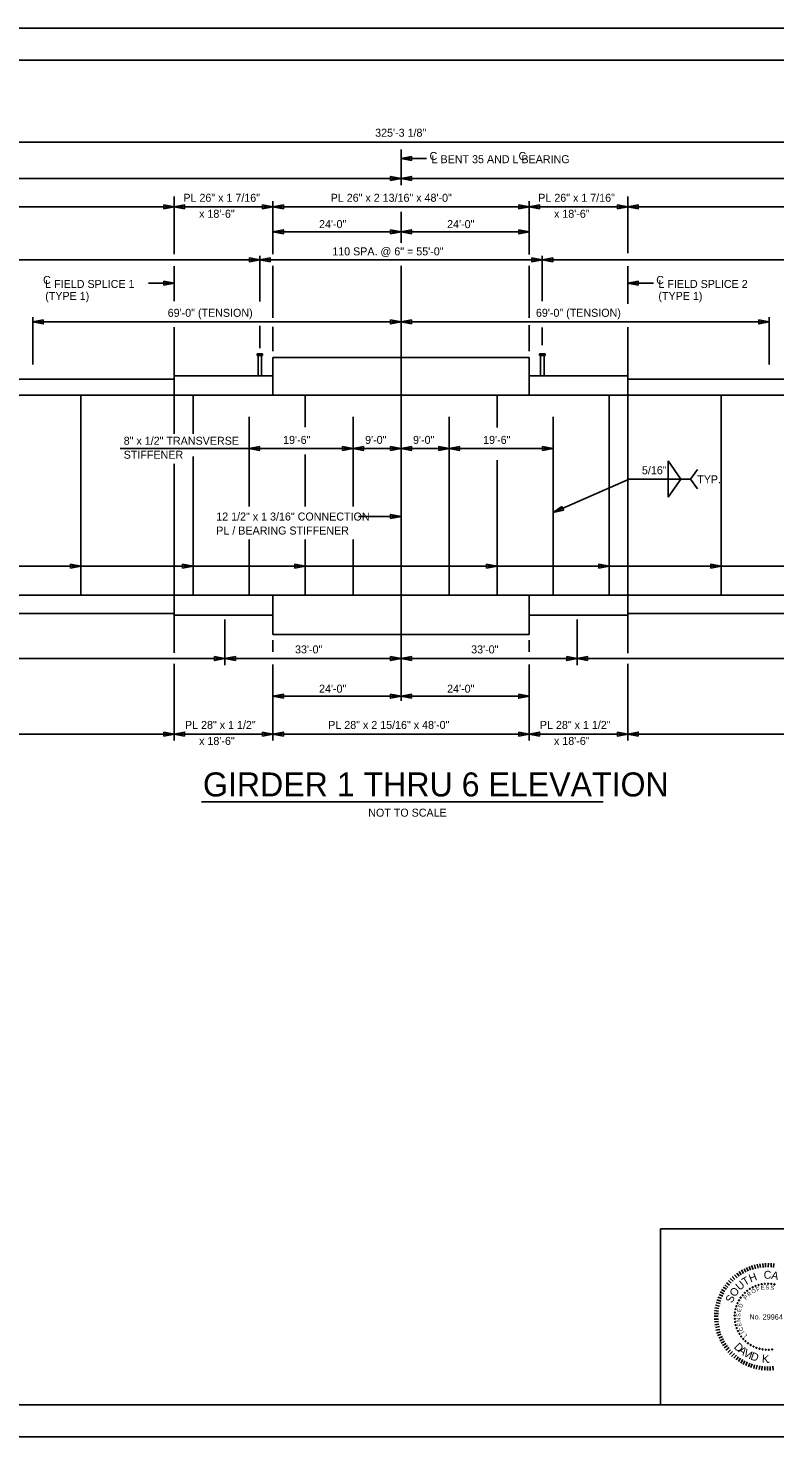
# Model space of a CAD drawing. Extents: x -305 to -161, y -187 to -99.
# Drawn here: x -254.1 to -207.5, y -187.5 to -99.5 of the extents above; entities that cross this region are included whole.
import ezdxf

# ---------------------------------------------------------------- set-up
doc = ezdxf.new("R2010")
doc.units = 0
for name, color, linetype in [('BR_AUTO DIMENSION', 7, 'Continuous'), ('BR_BORDER LINES', 7, 'Continuous'), ('BR_CENTER LINES', 7, 'Continuous'), ('BR_STRUCTURAL STEEL', 7, 'Continuous'), ('BR_TEXT', 7, 'Continuous'), ('Default', 7, 'Continuous'), ('Level 31', 7, 'Continuous')]:
    doc.layers.add(name, color=color, linetype=linetype)

msp = doc.modelspace()

# ---------------------------------------------------------------- linework, layer by layer
at = {"layer": 'BR_AUTO DIMENSION'}
for p, q in [((-285.058, -106.618), (-176.638, -106.618)), ((-230.848, -107.634), (-229.249, -107.634)), ((-285.058, -108.876), (-230.848, -108.876)), ((-230.848, -108.876), (-176.638, -108.876)), ((-245.014, -110.653), (-285.055, -110.653)), ((-238.848, -110.653), (-245.014, -110.653)), ((-238.848, -110.296), (-238.848, -113.612)), ((-238.848, -110.653), (-222.848, -110.653)), ((-222.848, -110.296), (-222.848, -113.63)), ((-222.848, -110.653), (-216.681, -110.653)), ((-176.638, -110.653), (-216.681, -110.653)), ((-230.848, -112.204), (-238.848, -112.204)), ((-222.848, -112.204), (-230.848, -112.204)), ((-178.638, -113.971), (-279.742, -113.971)), ((-239.668, -116.573), (-239.668, -113.71)), ((-238.848, -114.345), (-238.848, -117.575)), ((-222.848, -114.345), (-222.848, -117.575)), ((-222.028, -116.545), (-222.028, -113.71)), ((-245.014, -115.428), (-246.613, -115.428)), ((-216.681, -115.428), (-215.082, -115.428)), ((-253.848, -117.55), (-253.848, -120.501)), ((-253.848, -117.84), (-230.848, -117.84)), ((-207.848, -117.84), (-230.848, -117.84)), ((-207.848, -117.55), (-207.848, -120.501)), ((-239.668, -119.487), (-239.668, -118.076)), ((-238.848, -118.143), (-238.848, -119.661)), ((-222.848, -118.051), (-222.848, -119.661)), ((-222.028, -119.285), (-222.028, -118.194)), ((-248.394, -125.748), (-233.848, -125.748)), ((-233.848, -125.748), (-230.848, -125.748)), ((-230.848, -125.748), (-227.848, -125.748)), ((-227.848, -125.748), (-221.354, -125.748)), ((-214.174, -126.524), (-214.174, -128.791)), ((-214.174, -126.524), (-213.369, -127.657)), ((-212.766, -127.657), (-212.333, -127.05)), ((-216.59, -127.657), (-221.354, -129.746)), ((-216.59, -127.657), (-212.766, -127.657)), ((-214.174, -128.791), (-213.369, -127.657)), ((-212.766, -127.657), (-212.333, -128.265)), ((-230.848, -129.991), (-233.496, -129.991)), ((-182.854, -133.101), (-289.275, -133.101)), ((-241.848, -136.437), (-241.848, -139.273)), ((-219.848, -136.437), (-219.848, -139.273)), ((-238.848, -137.729), (-238.848, -138.442)), ((-222.848, -137.729), (-222.848, -138.442)), ((-241.848, -138.867), (-285.058, -138.867)), ((-230.848, -138.867), (-241.848, -138.867)), ((-219.848, -138.867), (-230.848, -138.867)), ((-176.638, -138.867), (-219.848, -138.867)), ((-238.848, -139.243), (-238.848, -143.986)), ((-222.848, -139.243), (-222.848, -143.986)), ((-230.848, -141.226), (-238.848, -141.226)), ((-222.848, -141.226), (-230.848, -141.226)), ((-285.055, -143.585), (-245.014, -143.585)), ((-245.014, -143.585), (-238.848, -143.585)), ((-238.848, -143.585), (-222.848, -143.585)), ((-222.848, -143.585), (-216.681, -143.585)), ((-216.681, -143.585), (-176.638, -143.585))]:
    msp.add_line(p, q, dxfattribs=at)
for points in [[(-230.198, -107.759), (-230.848, -107.634), (-230.198, -107.509)], [(-231.498, -109.001), (-230.848, -108.876), (-231.498, -108.751)], [(-230.198, -109.001), (-230.848, -108.876), (-230.198, -108.751)], [(-245.664, -110.778), (-245.014, -110.653), (-245.664, -110.528)], [(-244.364, -110.778), (-245.014, -110.653), (-244.364, -110.528)], [(-239.498, -110.778), (-238.848, -110.653), (-239.498, -110.528)], [(-238.198, -110.778), (-238.848, -110.653), (-238.198, -110.528)], [(-223.498, -110.778), (-222.848, -110.653), (-223.498, -110.528)], [(-222.198, -110.778), (-222.848, -110.653), (-222.198, -110.528)], [(-217.331, -110.778), (-216.681, -110.653), (-217.331, -110.528)], [(-216.031, -110.778), (-216.681, -110.653), (-216.031, -110.528)], [(-238.198, -112.329), (-238.848, -112.204), (-238.198, -112.079)], [(-231.498, -112.079), (-230.848, -112.204), (-231.498, -112.329)], [(-230.198, -112.329), (-230.848, -112.204), (-230.198, -112.079)], [(-223.498, -112.079), (-222.848, -112.204), (-223.498, -112.329)], [(-240.318, -114.096), (-239.668, -113.971), (-240.318, -113.846)], [(-239.018, -114.096), (-239.668, -113.971), (-239.018, -113.846)], [(-222.678, -114.096), (-222.028, -113.971), (-222.678, -113.846)], [(-221.378, -114.096), (-222.028, -113.971), (-221.378, -113.846)], [(-245.664, -115.553), (-245.014, -115.428), (-245.664, -115.303)], [(-216.031, -115.553), (-216.681, -115.428), (-216.031, -115.303)], [(-253.198, -117.715), (-253.848, -117.84), (-253.198, -117.965)], [(-231.498, -117.715), (-230.848, -117.84), (-231.498, -117.965)], [(-230.198, -117.965), (-230.848, -117.84), (-230.198, -117.715)], [(-208.498, -117.715), (-207.848, -117.84), (-208.498, -117.965)], [(-239.69, -125.623), (-240.34, -125.748), (-239.69, -125.873)], [(-234.498, -125.873), (-233.848, -125.748), (-234.498, -125.623)], [(-233.198, -125.623), (-233.848, -125.748), (-233.198, -125.873)], [(-231.498, -125.873), (-230.848, -125.748), (-231.498, -125.623)], [(-230.198, -125.623), (-230.848, -125.748), (-230.198, -125.873)], [(-228.498, -125.873), (-227.848, -125.748), (-228.498, -125.623)], [(-227.198, -125.623), (-227.848, -125.748), (-227.198, -125.873)], [(-222.004, -125.873), (-221.354, -125.748), (-222.004, -125.623)], [(-231.498, -130.116), (-230.848, -129.991), (-231.498, -129.866)], [(-220.809, -129.371), (-221.354, -129.746), (-220.708, -129.6)], [(-251.49, -133.226), (-250.84, -133.101), (-251.49, -132.976)], [(-244.49, -133.226), (-243.84, -133.101), (-244.49, -132.976)], [(-237.49, -133.226), (-236.84, -133.101), (-237.49, -132.976)], [(-225.504, -133.226), (-224.854, -133.101), (-225.504, -132.976)], [(-218.504, -133.226), (-217.854, -133.101), (-218.504, -132.976)], [(-211.504, -133.226), (-210.854, -133.101), (-211.504, -132.976)], [(-242.498, -138.742), (-241.848, -138.867), (-242.498, -138.992)], [(-241.198, -138.992), (-241.848, -138.867), (-241.198, -138.742)], [(-231.498, -138.742), (-230.848, -138.867), (-231.498, -138.992)], [(-230.198, -138.992), (-230.848, -138.867), (-230.198, -138.742)], [(-220.498, -138.742), (-219.848, -138.867), (-220.498, -138.992)], [(-219.198, -138.992), (-219.848, -138.867), (-219.198, -138.742)], [(-238.198, -141.351), (-238.848, -141.226), (-238.198, -141.101)], [(-231.498, -141.101), (-230.848, -141.226), (-231.498, -141.351)], [(-230.198, -141.351), (-230.848, -141.226), (-230.198, -141.101)], [(-223.498, -141.101), (-222.848, -141.226), (-223.498, -141.351)], [(-245.664, -143.46), (-245.014, -143.585), (-245.664, -143.71)], [(-244.364, -143.71), (-245.014, -143.585), (-244.364, -143.46)], [(-239.498, -143.46), (-238.848, -143.585), (-239.498, -143.71)], [(-238.198, -143.71), (-238.848, -143.585), (-238.198, -143.46)], [(-223.498, -143.46), (-222.848, -143.585), (-223.498, -143.71)], [(-222.198, -143.71), (-222.848, -143.585), (-222.198, -143.46)], [(-217.331, -143.46), (-216.681, -143.585), (-217.331, -143.71)], [(-216.031, -143.71), (-216.681, -143.585), (-216.031, -143.46)]]:
    msp.add_lwpolyline(points, close=True, dxfattribs=at)
at = {"layer": 'BR_BORDER LINES'}
for p, q in [((-163.178, -101.489), (-297.843, -101.489)), ((-214.64, -174.489), (-193.18, -174.489)), ((-214.64, -185.489), (-214.64, -174.489)), ((-297.843, -185.489), (-163.178, -185.489))]:
    msp.add_line(p, q, dxfattribs=at)
at = {"layer": 'BR_CENTER LINES'}
for p, q in [((-230.848, -107.059), (-230.848, -109.303)), ((-245.014, -109.997), (-245.014, -113.616)), ((-216.681, -109.997), (-216.681, -113.552)), ((-230.848, -110.967), (-230.848, -112.902)), ((-245.014, -114.353), (-245.014, -116.546)), ((-230.848, -114.337), (-230.848, -122.412)), ((-216.681, -114.353), (-216.681, -116.705)), ((-245.014, -118.172), (-245.014, -124.828)), ((-216.681, -118.172), (-216.681, -138.538)), ((-245.014, -126.695), (-245.014, -138.52)), ((-230.848, -134.912), (-230.848, -141.514)), ((-245.014, -139.198), (-245.014, -143.986)), ((-216.681, -139.198), (-216.681, -143.986))]:
    msp.add_line(p, q, dxfattribs=at)
at = {"layer": 'BR_STRUCTURAL STEEL'}
for p, q in [((-238.848, -120.069), (-222.848, -120.069)), ((-238.848, -122.412), (-238.848, -120.069)), ((-222.848, -122.412), (-222.848, -120.069)), ((-285.058, -121.423), (-245.014, -121.423)), ((-245.014, -121.215), (-245.014, -122.412)), ((-245.014, -121.215), (-238.848, -121.215)), ((-222.848, -121.215), (-216.681, -121.215)), ((-216.681, -121.215), (-216.681, -122.412)), ((-216.681, -121.423), (-176.638, -121.423)), ((-285.058, -122.412), (-176.638, -122.412)), ((-250.84, -122.412), (-250.84, -134.912)), ((-243.84, -122.412), (-243.84, -124.828)), ((-236.84, -122.412), (-236.84, -124.407)), ((-230.848, -122.412), (-230.848, -134.912)), ((-224.854, -122.412), (-224.854, -124.436)), ((-217.854, -122.412), (-217.854, -134.912)), ((-210.854, -122.412), (-210.854, -134.912)), ((-240.34, -123.779), (-240.34, -129.362)), ((-233.848, -123.779), (-233.848, -129.362)), ((-227.848, -123.779), (-227.848, -134.912)), ((-221.354, -123.779), (-221.354, -134.912)), ((-243.84, -126.24), (-243.84, -134.912)), ((-236.84, -126.13), (-236.84, -129.362)), ((-224.854, -126.467), (-224.854, -134.912)), ((-240.34, -131.431), (-240.34, -134.912)), ((-236.84, -131.431), (-236.84, -134.912)), ((-233.848, -131.431), (-233.848, -134.912)), ((-285.058, -134.912), (-176.638, -134.912)), ((-245.014, -134.912), (-245.014, -136.162)), ((-238.848, -137.36), (-238.848, -134.912)), ((-222.848, -137.36), (-222.848, -134.912)), ((-216.681, -136.162), (-216.681, -134.912)), ((-285.058, -136.058), (-245.014, -136.058)), ((-245.014, -136.162), (-238.848, -136.162)), ((-222.848, -136.162), (-216.681, -136.162)), ((-216.681, -136.058), (-176.638, -136.058)), ((-238.848, -137.36), (-222.848, -137.36))]:
    msp.add_line(p, q, dxfattribs=at)
at = {"layer": 'BR_TEXT'}
for p, q in [((-243.307, -147.82), (-218.234, -147.82)), ((-209.02, -177.076), (-209.103, -176.842)), ((-208.861, -177.026), (-208.949, -176.795)), ((-208.717, -176.986), (-208.77, -176.742)), ((-208.552, -176.946), (-208.608, -176.709)), ((-208.394, -176.917), (-208.429, -176.673)), ((-208.236, -176.901), (-208.251, -176.657)), ((-208.077, -176.892), (-208.075, -176.634)), ((-207.909, -176.883), (-207.907, -176.636)), ((-207.741, -176.895), (-207.732, -176.637)), ((-207.58, -176.906), (-207.561, -176.663)), ((-210.228, -177.894), (-210.402, -177.724)), ((-210.11, -177.771), (-210.287, -177.594)), ((-209.993, -177.662), (-210.159, -177.482)), ((-209.861, -177.564), (-210.021, -177.363)), ((-209.726, -177.462), (-209.883, -177.258)), ((-209.602, -177.377), (-209.724, -177.16)), ((-209.461, -177.282), (-209.582, -177.065)), ((-209.323, -177.211), (-209.427, -176.987)), ((-209.175, -177.144), (-209.269, -176.92)), ((-210.756, -178.699), (-210.985, -178.598)), ((-210.686, -178.552), (-210.912, -178.441)), ((-210.617, -178.416), (-210.832, -178.287)), ((-210.519, -178.269), (-210.734, -178.137)), ((-210.432, -178.153), (-210.63, -177.993)), ((-210.328, -178.02), (-210.526, -177.864)), ((-210.996, -179.47), (-211.24, -179.437)), ((-210.954, -179.326), (-211.204, -179.262)), ((-210.925, -179.158), (-211.168, -179.098)), ((-210.876, -179.014), (-211.122, -178.923)), ((-210.826, -178.853), (-211.059, -178.766)), ((-211.029, -180.129), (-211.286, -180.133)), ((-211.034, -179.957), (-211.285, -179.955)), ((-211.026, -179.792), (-211.284, -179.79)), ((-211.02, -180.283), (-211.267, -180.312)), ((-211.015, -179.634), (-211.261, -179.605)), ((-211.004, -180.448), (-211.248, -180.484)), ((-210.964, -180.606), (-211.215, -180.659)), ((-210.938, -180.775), (-211.182, -180.831)), ((-210.891, -180.923), (-211.139, -181.006)), ((-210.845, -181.077), (-211.079, -181.161)), ((-210.777, -181.226), (-211.008, -181.334)), ((-210.71, -181.37), (-210.937, -181.489)), ((-210.642, -181.519), (-210.859, -181.644)), ((-210.547, -181.667), (-210.765, -181.792)), ((-210.462, -181.784), (-210.663, -181.93)), ((-210.361, -181.919), (-210.561, -182.075)), ((-210.262, -182.054), (-210.439, -182.217)), ((-210.146, -182.158), (-210.326, -182.338)), ((-210.031, -182.279), (-210.2, -182.463)), ((-209.901, -182.383), (-210.064, -182.57)), ((-209.768, -182.487), (-209.927, -182.678)), ((-209.645, -182.574), (-209.77, -182.782)), ((-209.505, -182.664), (-209.63, -182.879)), ((-209.368, -182.744), (-209.477, -182.967)), ((-209.221, -182.814), (-209.319, -183.037)), ((-209.068, -182.884), (-209.155, -183.11)), ((-208.91, -182.933), (-209.001, -183.166)), ((-208.766, -182.983), (-208.823, -183.219)), ((-208.602, -183.011), (-208.662, -183.258)), ((-208.444, -183.058), (-208.484, -183.29)), ((-208.287, -183.076), (-208.306, -183.323)), ((-208.129, -183.087), (-208.131, -183.335)), ((-207.961, -183.099), (-207.963, -183.343)), ((-207.792, -183.09), (-207.787, -183.338)), ((-207.631, -183.081), (-207.616, -183.329))]:
    msp.add_line(p, q, dxfattribs=at)
for centre, start, end in [((-209.51, -178.639), 49.37299, 229.37299), ((-209.51, -178.639), 229.37299, 49.37299), ((-209.373, -178.495), 43.83453, 223.83453), ((-209.373, -178.495), 223.83453, 43.83453), ((-209.223, -178.364), 38.29606, 218.29606), ((-209.223, -178.364), 218.29606, 38.29606), ((-209.06, -178.248), 32.7576, 212.7576), ((-209.06, -178.248), 212.7576, 32.7576), ((-208.887, -178.149), 27.21914, 207.21914), ((-208.887, -178.149), 207.21914, 27.21914), ((-208.706, -178.067), 21.68068, 201.68068), ((-208.706, -178.067), 201.68068, 21.68068), ((-208.517, -178.003), 16.14222, 196.14222), ((-208.517, -178.003), 196.14222, 16.14222), ((-208.323, -177.957), 10.60376, 190.60376), ((-208.323, -177.957), 190.60376, 10.60376), ((-208.126, -177.93), 5.06529, 185.06529), ((-208.126, -177.93), 185.06529, 5.06529), ((-207.926, -177.923), 359.52683, 179.52683), ((-207.926, -177.923), 179.52683, 359.52683), ((-207.727, -177.934), 353.98837, 173.98837), ((-207.727, -177.934), 173.98837, 353.98837), ((-207.531, -177.965), 168.44991, 348.44991), ((-207.531, -177.965), 348.44991, 168.44991), ((-209.957, -179.52), 77.06529, 257.06529), ((-209.957, -179.52), 257.06529, 77.06529), ((-209.903, -179.328), 71.52683, 251.52683), ((-209.903, -179.328), 251.52683, 71.52683), ((-209.83, -179.142), 65.98837, 245.98837), ((-209.83, -179.142), 245.98837, 65.98837), ((-209.74, -178.964), 60.44991, 240.44991), ((-209.74, -178.964), 240.44991, 60.44991), ((-209.633, -178.796), 54.91145, 234.91145), ((-209.633, -178.796), 234.91145, 54.91145), ((-210.009, -179.914), 88.14222, 268.14222), ((-210.006, -180.114), 93.68068, 273.68068), ((-209.993, -179.716), 82.60376, 262.60376), ((-209.984, -180.312), 99.21914, 279.21914), ((-210.009, -179.914), 268.14222, 88.14222), ((-210.006, -180.114), 273.68068, 93.68068), ((-209.993, -179.716), 262.60376, 82.60376), ((-209.984, -180.312), 279.21914, 99.21914), ((-209.943, -180.507), 104.7576, 284.7576), ((-209.943, -180.507), 284.7576, 104.7576), ((-209.884, -180.697), 110.29606, 290.29606), ((-209.884, -180.697), 290.29606, 110.29606), ((-209.806, -180.881), 115.83453, 295.83453), ((-209.806, -180.881), 295.83453, 115.83453), ((-209.711, -181.056), 121.37299, 301.37299), ((-209.711, -181.056), 301.37299, 121.37299), ((-209.599, -181.221), 126.91145, 306.91145), ((-209.599, -181.221), 306.91145, 126.91145), ((-209.472, -181.375), 132.44991, 312.44991), ((-209.472, -181.375), 312.44991, 132.44991), ((-209.331, -181.515), 137.98837, 317.98837), ((-209.331, -181.515), 317.98837, 137.98837), ((-209.177, -181.642), 143.52683, 323.52683), ((-209.177, -181.642), 323.52683, 143.52683), ((-209.011, -181.753), 149.06529, 329.06529), ((-209.011, -181.753), 329.06529, 149.06529), ((-208.836, -181.847), 154.60376, 334.60376), ((-208.836, -181.847), 334.60376, 154.60376), ((-208.652, -181.924), 160.14222, 340.14222), ((-208.652, -181.924), 340.14222, 160.14222), ((-208.462, -181.983), 165.68068, 345.68068), ((-208.462, -181.983), 345.68068, 165.68068), ((-208.267, -182.023), 171.21914, 351.21914), ((-208.267, -182.023), 351.21914, 171.21914), ((-208.068, -182.045), 356.7576, 176.7576), ((-208.068, -182.045), 176.7576, 356.7576), ((-207.869, -182.047), 2.29606, 182.29606), ((-207.869, -182.047), 182.29606, 2.29606), ((-207.67, -182.029), 7.83453, 187.83453), ((-207.67, -182.029), 187.83453, 7.83453)]:
    msp.add_arc(centre, 0.028, start, end, dxfattribs=at)
at = {"layer": 'Default'}
for p, q in [((-239.839, -119.84), (-239.839, -119.933)), ((-239.839, -119.84), (-239.496, -119.84)), ((-239.839, -119.933), (-239.496, -119.933)), ((-239.777, -119.933), (-239.777, -121.215)), ((-239.558, -119.933), (-239.558, -121.215)), ((-239.496, -119.84), (-239.496, -119.933)), ((-222.199, -119.84), (-222.199, -119.933)), ((-222.199, -119.84), (-221.856, -119.84)), ((-222.199, -119.933), (-221.856, -119.933)), ((-222.137, -119.933), (-222.137, -121.215)), ((-221.918, -119.933), (-221.918, -121.215)), ((-221.856, -119.84), (-221.856, -119.933))]:
    msp.add_line(p, q, dxfattribs=at)
at = {"layer": 'Level 31'}
msp.add_lwpolyline([(-305.176, -187.489), (-161.176, -187.489), (-161.176, -99.489), (-305.176, -99.489)], close=True, dxfattribs=at)

# ---------------------------------------------------------------- texts
at = {"layer": 'BR_AUTO DIMENSION'}
for s, p in [('325\'-3 1/8"', (-232.465, -106.272)), ('PL 26" x 1 7/16"', (-244.444, -110.334)), ('PL 26" x 2 13/16" x 48\'-0"', (-235.244, -110.334)), ('PL 26" x 1 7/16"', (-222.278, -110.334)), (' x 18\'-6"', (-243.647, -111.334)), (' x 18\'-6"', (-221.481, -111.334)), ('24\'-0"', (-235.969, -111.979)), ('24\'-0"', (-227.969, -111.979)), ('110 SPA. @ 6" = 55\'-0"', (-235.144, -113.683)), ('69\'-0" (TENSION)', (-222.423, -117.521)), ('19\'-6"', (-238.215, -125.459)), ('9\'-0"', (-233.093, -125.459)), ('9\'-0"', (-230.099, -125.459)), ('19\'-6"', (-225.722, -125.459)), ('5/16"', (-215.802, -127.357)), ('TYP.', (-212.349, -127.924)), ('33\'-0"', (-237.469, -138.548)), ('24\'-0"', (-235.969, -141.001)), ('24\'-0"', (-227.969, -141.001)), ('PL 28" x 1 1/2"', (-244.343, -143.266)), ('PL 28" x 2 15/16" x 48\'-0"', (-235.398, -143.266)), ('PL 28" x 1 1/2"', (-222.177, -143.266)), (' x 18\'-6"', (-243.647, -144.266)), (' x 18\'-6"', (-221.481, -144.266))]:
    msp.add_text(s, height=0.5, rotation=360, dxfattribs=at).set_placement(p)
for s, p in [('69\'-0" (TENSION)', (-245.423, -117.521)), ('33\'-0"', (-226.469, -138.548))]:
    msp.add_text(s, height=0.5, dxfattribs=at).set_placement(p)
at = {"layer": 'BR_TEXT'}
for s, height, rotation, p in [('C', 0.5, 360, (-229.068, -107.723)), ('C', 0.5, 360, (-223.51, -107.723)), ('L BENT 35 AND L BEARING', 0.5, 360, (-228.94, -107.924)), ('C', 0.5, 360, (-253.207, -115.468)), ('L FIELD SPLICE 1 ', 0.5, 360, (-253.072, -115.718)), ('C', 0.5, 360, (-214.908, -115.468)), ('L FIELD SPLICE 2', 0.5, 360, (-214.773, -115.718)), ('(TYPE 1)', 0.5, 360, (-253.072, -116.468)), ('(TYPE 1)', 0.5, 360, (-214.773, -116.468)), ('8" x 1/2" TRANSVERSE ', 0.5, 360, (-248.171, -125.513)), ('STIFFENER', 0.5, 360, (-248.171, -126.388)), ('12 1/2" x 1 3/16" CONNECTION ', 0.5, 360, (-242.389, -130.248)), ('PL / BEARING STIFFENER', 0.5, 360, (-242.389, -131.123)), ('U', 0.496, 40.80225, (-209.694, -178.375)), ('T', 0.496, 30.49921, (-209.37, -178.076)), ('H', 0.496, 20.36371, (-209.018, -177.846)), ('C', 0.496, 359.54822, (-208.2, -177.612)), ('A', 0.496, 348.19813, (-207.755, -177.609)), ('S', 0.496, 63.25114, (-210.174, -179.173)), ('O', 0.496, 52.0267, (-209.993, -178.79)), ('R', 0.249, 40.39491, (-209.107, -178.737)), ('O', 0.249, 30.84774, (-208.882, -178.561)), ('F', 0.249, 20.61271, (-208.613, -178.417)), ('E', 0.249, 11.41035, (-208.352, -178.33)), ('S', 0.249, 2.20798, (-208.081, -178.286)), ('S', 0.249, 352.66081, (-207.796, -178.287)), ('E', 0.249, 78.23881, (-209.633, -179.715)), ('D', 0.249, 69.03644, (-209.567, -179.448)), ('P', 0.249, 49.94209, (-209.299, -178.947)), ('S', 0.249, 87.78598, (-209.656, -179.999)), ('N', 0.249, 97.33316, (-209.632, -180.283)), ('E', 0.249, 106.53552, (-209.564, -180.549)), ('No. 29964', 0.327, 359.52683, (-209.092, -180.153)), ('C', 0.249, 116.42662, (-209.444, -180.819)), ('I', 0.249, 121.10107, (-209.372, -180.939)), ('L', 0.249, 129.95951, (-209.209, -181.147)), ('D', 0.494, 315.40526, (-210.091, -181.91)), ('A', 0.494, 322.83772, (-209.825, -182.173)), ('V', 0.494, 330.51792, (-209.516, -182.405)), ('I', 0.494, 338.19813, (-209.179, -182.595)), ('D', 0.494, 340.79949, (-209.06, -182.648)), ('K', 0.494, 356.09796, (-208.319, -182.851)), ('.', 0.494, 3.15879, (-207.964, -182.876))]:
    msp.add_text(s, height=height, rotation=rotation, dxfattribs=at).set_placement(p)
for s, height, p in [('GIRDER 1 THRU 6 ELEVATION', 1.5, (-243.22, -147.483)), ('NOT TO SCALE', 0.5, (-232.898, -148.747))]:
    msp.add_text(s, height=height, dxfattribs=at).set_placement(p)

doc.saveas('drawing.dxf')
